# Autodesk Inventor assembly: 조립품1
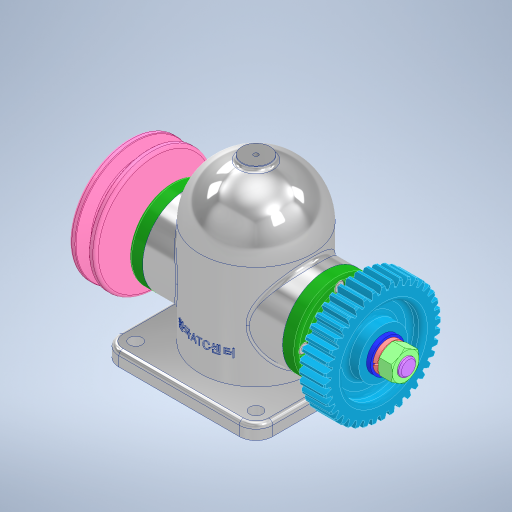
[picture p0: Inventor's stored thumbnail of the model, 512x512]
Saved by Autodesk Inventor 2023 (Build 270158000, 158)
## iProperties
Created: 2025-04
Part Number: 조립품1
Document SubType Name: Assembly
Designer: ADMIN_PC
Author: ADMIN_PC
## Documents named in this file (14)
- C:\Users\ADMIN_PC\Desktop\750406V1010\조립품1.iam
- C:\Users\ADMIN_PC\Desktop\750406V1010\부품.ipt
- C:\Users\ADMIN_PC\Desktop\750406V1010\깊은 홈 볼 베어링 6203.ipt
- C:\Users\ADMIN_PC\Desktop\750406V1010\축.ipt
- C:\Users\ADMIN_PC\Desktop\750406V1010\커버.ipt
- C:\Users\ADMIN_PC\Desktop\750406V1010\오일 실 26 38 8.ipt
- C:\Users\ADMIN_PC\Desktop\750406V1010\6각 구멍붙이 볼트 M4x12.ipt
- C:\Users\ADMIN_PC\Desktop\750406V1010\칼라.ipt
- C:\Users\ADMIN_PC\Desktop\750406V1010\평행 키 5x5x12.ipt
- C:\Users\ADMIN_PC\Desktop\750406V1010\스퍼기어.ipt
- C:\Users\ADMIN_PC\Desktop\750406V1010\V 벨트 풀리.ipt
- C:\Users\ADMIN_PC\Desktop\750406V1010\평와셔 M12.ipt
- C:\Users\ADMIN_PC\Desktop\750406V1010\스프링 와셔 M12.ipt
- C:\Users\ADMIN_PC\Desktop\750406V1010\6각 너트 M12x1.ipt
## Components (11 placed, 3 different names)
1. 6각 구멍붙이 볼트 M4x12:1
2. 6각 구멍붙이 볼트 M4x12:2
3. 6각 구멍붙이 볼트 M4x12:3
4. 6각 구멍붙이 볼트 M4x12:4
5. 6각 구멍붙이 볼트 M4x12:5
6. 6각 구멍붙이 볼트 M4x12:6
7. 6각 구멍붙이 볼트 M4x12:7
8. 6각 구멍붙이 볼트 M4x12:8
9. V 벨트 풀리:1
10. 6각 너트 M12x1:1
11. 6각 너트 M12x1:2
